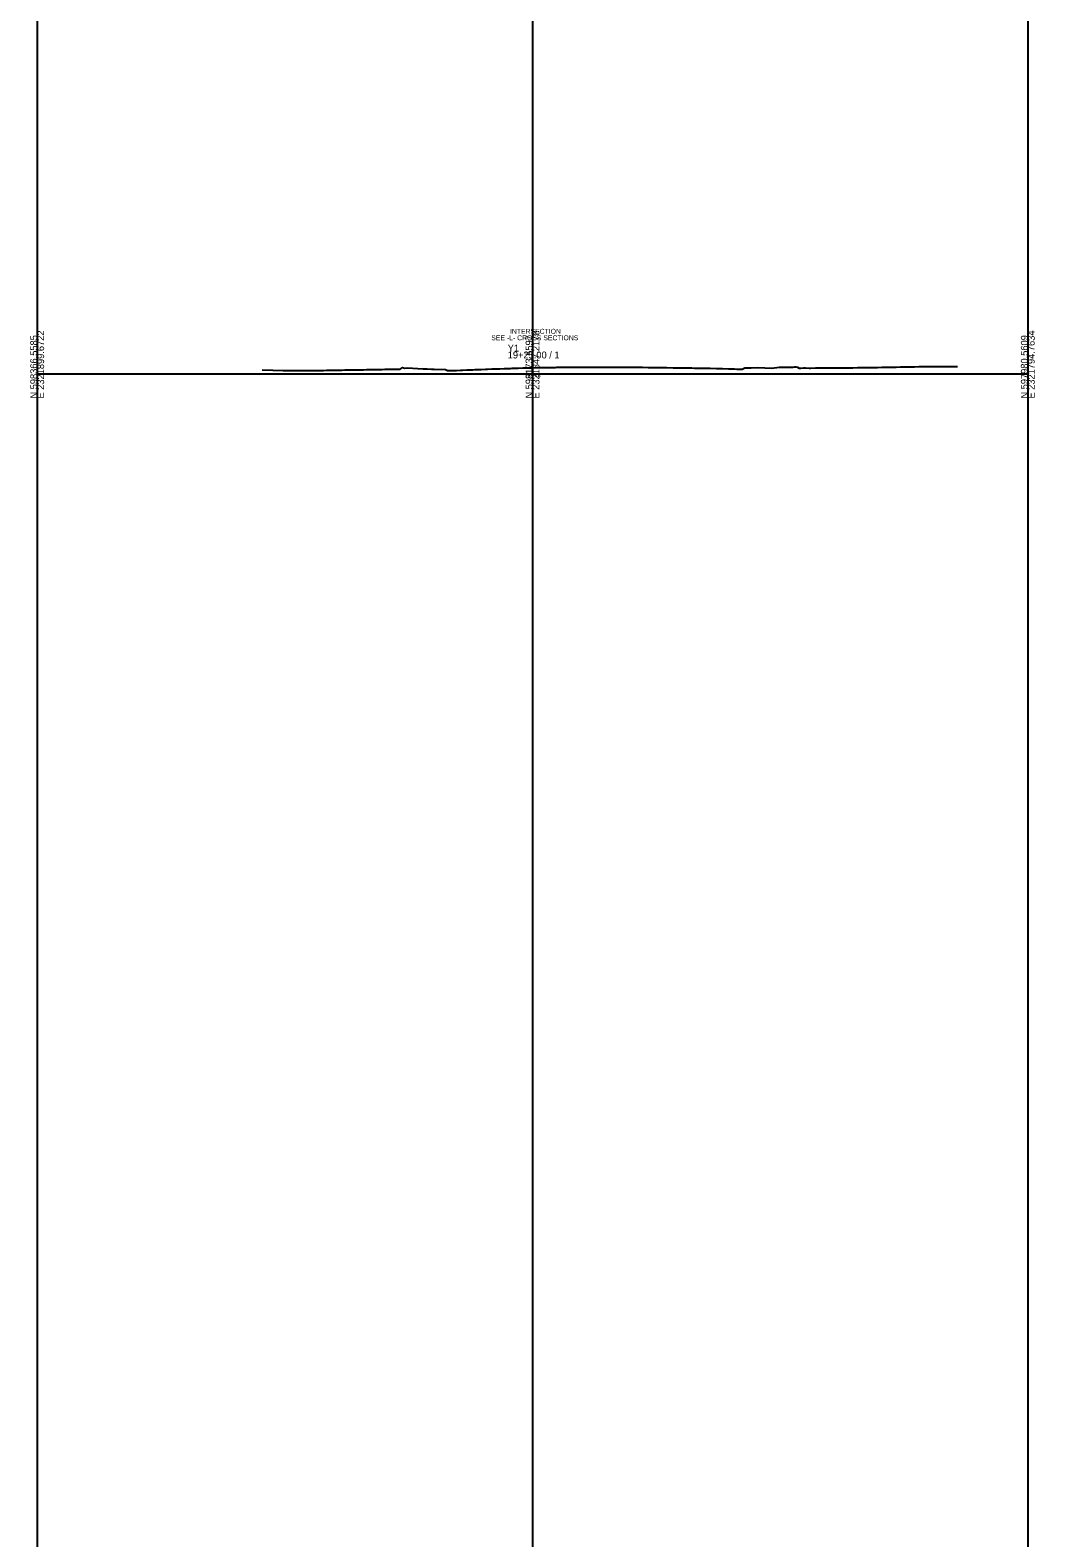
# Model space of a CAD drawing. Extents: x -26 to 2321974, y -203 to 598218.
# Drawn here: x 997 to 1403, y 8030 to 8639 of the extents above; entities that cross this region are included whole.
import ezdxf

# ---------------------------------------------------------------- set-up
doc = ezdxf.new("R2010")
doc.units = 0
for name, color, linetype in [('Default', 7, 'Continuous'), ('Exist CMT Pavement', 7, 'Continuous'), ('Exist Cross Section Cell', 7, 'Continuous'), ('Exist XS Center Line Elevation Label', 7, 'Continuous'), ('Exist XS Ground Line', 7, 'Continuous'), ('Prop XS Exc Vertical Line 1', 7, 'Continuous'), ('Prop XS Exc Vertical Line 2', 7, 'Continuous'), ('Prop XS Exc Vertical Line 3', 7, 'Continuous'), ('Prop XS Shear Point Element', 7, 'Continuous')]:
    doc.layers.add(name, color=color, linetype=linetype)

msp = doc.modelspace()

# ---------------------------------------------------------------- linework, layer by layer
at = {"layer": 'Exist CMT Pavement'}
for p, q in [((1200, 8502.46), (1200, 8502.56)), ((1200, 8502.56), (1200.1, 8502.56)), ((1200.1, 8502.56), (1200.1, 8502.47))]:
    msp.add_line(p, q, dxfattribs=at)
at = {"layer": 'Exist Cross Section Cell'}
for p, q in [((1200, 8500), (1200, 8509)), ((1000, 8500), (1200, 8500)), ((1200, 8500), (1400, 8500))]:
    msp.add_line(p, q, dxfattribs=at)
at = {"layer": 'Exist XS Ground Line'}
msp.add_lwpolyline([(1090.81, 8501.54), (1095.15, 8501.46), (1099.27, 8501.36), (1101.62, 8501.29), (1102.02, 8501.28), (1102.48, 8501.28), (1106.23, 8501.33), (1106.57, 8501.33), (1106.97, 8501.33), (1107.44, 8501.33), (1110.99, 8501.37), (1112.79, 8501.38), (1113.13, 8501.39), (1114.47, 8501.39), (1115.61, 8501.4), (1116.77, 8501.42), (1118.09, 8501.45), (1119.27, 8501.46), (1120.56, 8501.49), (1121.77, 8501.5), (1123.04, 8501.52), (1124.27, 8501.54), (1125.52, 8501.56), (1126.77, 8501.57), (1128.04, 8501.59), (1129.27, 8501.62), (1130.48, 8501.64), (1131.77, 8501.66), (1132.95, 8501.69), (1134.27, 8501.72), (1135.43, 8501.74), (1136.77, 8501.77), (1138.13, 8501.78), (1139.27, 8501.8), (1140.39, 8501.81), (1141.77, 8501.82), (1143.17, 8501.83), (1143.5, 8501.83), (1144.87, 8501.82), (1145.38, 8501.83), (1146.6, 8501.86), (1147.31, 8502.35), (1147.51, 8502.49), (1148.4, 8502.29), (1149.57, 8502.36), (1153.72, 8502.21), (1155.86, 8502.05), (1157.46, 8501.95), (1159.15, 8501.84), (1160.25, 8501.81), (1164.89, 8501.73), (1165.19, 8501.55), (1165.64, 8501.31), (1167.16, 8501.33), (1167.7, 8501.32), (1168.91, 8501.38), (1169.27, 8501.4), (1170.92, 8501.47), (1171.77, 8501.5), (1173.44, 8501.57), (1174.27, 8501.6), (1175.97, 8501.66), (1176.77, 8501.69), (1178.49, 8501.75), (1179.27, 8501.78), (1181.01, 8501.85), (1181.77, 8501.88), (1183.54, 8501.95), (1184.27, 8501.98), (1186.06, 8502.04), (1186.77, 8502.07), (1188.58, 8502.13), (1189.27, 8502.15), (1191.1, 8502.21), (1191.77, 8502.23), (1193.63, 8502.29), (1194.27, 8502.31), (1196.15, 8502.36), (1196.77, 8502.38), (1197.38, 8502.4), (1199.27, 8502.45), (1200, 8502.46), (1201.77, 8502.5), (1202.34, 8502.52), (1204.27, 8502.55), (1206.24, 8502.57), (1206.77, 8502.58), (1208.76, 8502.6), (1209.27, 8502.61), (1209.77, 8502.62), (1211.77, 8502.64), (1212.25, 8502.64), (1214.27, 8502.66), (1214.73, 8502.67), (1216.77, 8502.69), (1218.85, 8502.7), (1219.27, 8502.7), (1219.68, 8502.7), (1221.77, 8502.71), (1222.16, 8502.72), (1224.27, 8502.72), (1224.64, 8502.72), (1226.77, 8502.73), (1228.94, 8502.73), (1229.27, 8502.73), (1229.59, 8502.73), (1232.07, 8502.74), (1234.55, 8502.73), (1236.77, 8502.72), (1239.5, 8502.69), (1241.77, 8502.67), (1244.46, 8502.63), (1246.77, 8502.6), (1249.27, 8502.57), (1251.77, 8502.54), (1254.27, 8502.51), (1256.85, 8502.48), (1259.36, 8502.45), (1259.99, 8502.45), (1261.8, 8502.41), (1264.27, 8502.36), (1265.46, 8502.34), (1266.77, 8502.31), (1269.31, 8502.27), (1271.77, 8502.22), (1274.27, 8502.16), (1276.77, 8502.1), (1279.19, 8502.04), (1281.53, 8501.96), (1282.57, 8501.94), (1284.61, 8501.9), (1285.8, 8502.35), (1286.23, 8502.4), (1287.39, 8502.41), (1288.26, 8502.45), (1290.92, 8502.52), (1296.62, 8502.33), (1299.6, 8502.64), (1305.2, 8502.72), (1305.95, 8502.77), (1306.38, 8502.77), (1306.98, 8502.75), (1307.73, 8502.33), (1308.31, 8502.34), (1309.47, 8502.36), (1310.19, 8502.36), (1311.77, 8502.34), (1312.19, 8502.34), (1314.27, 8502.35), (1316.32, 8502.37), (1316.77, 8502.37), (1317.24, 8502.37), (1319.27, 8502.4), (1321.28, 8502.41), (1321.78, 8502.41), (1323.75, 8502.42), (1324.27, 8502.43), (1326.23, 8502.44), (1326.78, 8502.44), (1327.33, 8502.45), (1329.28, 8502.47), (1331.19, 8502.49), (1331.78, 8502.5), (1333.66, 8502.52), (1334.28, 8502.53), (1336.14, 8502.56), (1336.78, 8502.56), (1337.42, 8502.57), (1339.28, 8502.6), (1341.1, 8502.63), (1341.78, 8502.64), (1343.58, 8502.66), (1344.28, 8502.68), (1346.05, 8502.71), (1346.78, 8502.72), (1348.53, 8502.76), (1349.28, 8502.77), (1350.03, 8502.79), (1351.78, 8502.82), (1353.49, 8502.85), (1354.28, 8502.87), (1355.97, 8502.89), (1356.78, 8502.91), (1358.44, 8502.93), (1359.28, 8502.94), (1360.12, 8502.95), (1361.78, 8502.97), (1363.4, 8502.99), (1364.28, 8502.99), (1365.88, 8503), (1366.78, 8503), (1368.36, 8502.99), (1369.28, 8502.99), (1370.83, 8502.99), (1371.6, 8502.99)], dxfattribs=at)
at = {"layer": 'Prop XS Exc Vertical Line 1'}
msp.add_line((1000, 9901.81), (1000, -202.52), dxfattribs=at)
at = {"layer": 'Prop XS Exc Vertical Line 2'}
msp.add_line((1200, 9901.81), (1200, -202.52), dxfattribs=at)
at = {"layer": 'Prop XS Exc Vertical Line 3'}
msp.add_line((1400, 9901.81), (1400, -202.52), dxfattribs=at)

# ---------------------------------------------------------------- texts
at = {"layer": 'Default'}
msp.add_text('-', height=0.0001, dxfattribs=at).set_placement((1000, 8500))
at = {"layer": 'Exist Cross Section Cell'}
for s, p in [('E 2321847.2178', (1202.8, 8490)), ('E 2321794.7634', (1402.8, 8490)), ('N 598366.5585', (1000, 8490)), ('E 2321899.6722', (1002.8, 8490)), ('N 598173.5597', (1200, 8490)), ('N 597980.5609', (1400, 8490))]:
    msp.add_text(s, height=2.8, rotation=90, dxfattribs=at).set_placement(p)
for s, p in [('Y1', (1190, 8509)), ('19+25.00 / 1', (1190, 8506.2))]:
    msp.add_text(s, height=2.8, dxfattribs=at).set_placement(p)
at = {"layer": 'Exist XS Center Line Elevation Label'}
msp.add_text('139.46', height=1.5, dxfattribs=at).set_placement((1196.91, 8498.46))
at = {"layer": 'Prop XS Shear Point Element'}
for s, p in [('INTERSECTION', (1190.9, 8516.16)), ('SEE -L- CROSS SECTIONS', (1183.36, 8513.54))]:
    msp.add_text(s, height=2, rotation=360, dxfattribs=at).set_placement(p)

doc.saveas('drawing.dxf')
